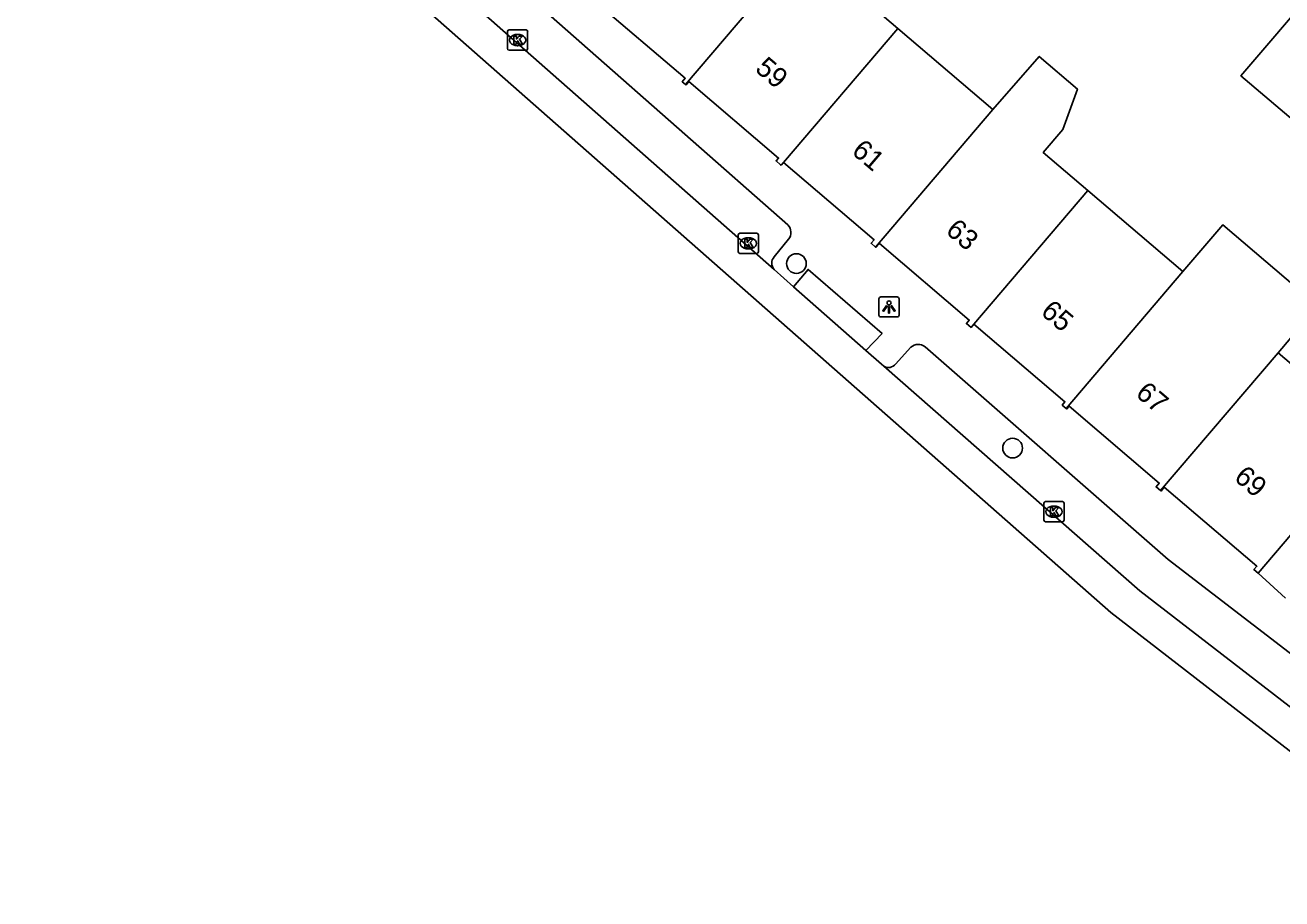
# Model space of a CAD drawing. Extents: x 162074 to 163034, y 381824 to 382557.
# Drawn here: x 162125.4 to 162187.8, y 382110.6 to 382154 of the extents above; entities that cross this region are included whole.
import ezdxf

# ---------------------------------------------------------------- set-up
doc = ezdxf.new("R2010")
doc.units = 0
for name, color, linetype in [('IMGEO_Boom', 7, 'Continuous'), ('IMGEO_Kolk', 7, 'Continuous'), ('IMGEO_Lichtpunt', 7, 'Continuous'), ('IMGEO_Pand', 7, 'Continuous'), ('IMGEO_Pand_nummerreeks', 7, 'Continuous'), ('IMGEO_Rijbaan_lokaal_gesloten', 7, 'Continuous'), ('IMGEO_Voetpad_open', 7, 'Continuous')]:
    doc.layers.add(name, color=color, linetype=linetype)

msp = doc.modelspace()

# ---------------------------------------------------------------- linework, layer by layer
at = {"layer": 'IMGEO_Boom'}
for centre in [(162163.658, 382142.201), (162174.394, 382133.032)]:
    msp.add_circle(centre, 0.489, dxfattribs=at)
at = {"layer": 'IMGEO_Kolk'}
for p, q in [((162149.309, 382152.875), (162149.309, 382153.727)), ((162149.384, 382153.801), (162150.236, 382153.801)), ((162149.797, 382153.581), (162149.822, 382153.581)), ((162150.31, 382153.727), (162150.31, 382152.875)), ((162150.236, 382152.801), (162149.384, 382152.801)), ((162149.82, 382153.021), (162149.795, 382153.021)), ((162160.769, 382142.779), (162160.769, 382143.631)), ((162160.844, 382143.705), (162161.696, 382143.705)), ((162161.257, 382143.485), (162161.282, 382143.485)), ((162161.77, 382143.631), (162161.77, 382142.779)), ((162161.696, 382142.705), (162160.844, 382142.705)), ((162161.28, 382142.925), (162161.255, 382142.925)), ((162175.946, 382129.452), (162175.946, 382130.304)), ((162176.021, 382130.378), (162176.873, 382130.378)), ((162176.434, 382130.158), (162176.459, 382130.158)), ((162176.947, 382130.304), (162176.947, 382129.452)), ((162176.457, 382129.598), (162176.432, 382129.598)), ((162176.873, 382129.378), (162176.021, 382129.378))]:
    msp.add_line(p, q, dxfattribs=at)
for points in [[(162149.309, 382152.875), (162149.309, 382153.727)], [(162149.384, 382153.801), (162150.236, 382153.801)], [(162149.63, 382153.501), (162149.753, 382153.501), (162149.753, 382153.35), (162149.883, 382153.501), (162150.047, 382153.501), (162149.901, 382153.35), (162150.054, 382153.101), (162149.902, 382153.101), (162149.817, 382153.265), (162149.753, 382153.198), (162149.753, 382153.101), (162149.63, 382153.101), (162149.63, 382153.501)], [(162150.31, 382153.727), (162150.31, 382152.875)], [(162150.236, 382152.801), (162149.384, 382152.801)], [(162160.769, 382142.779), (162160.769, 382143.631)], [(162160.844, 382143.705), (162161.696, 382143.705)], [(162161.09, 382143.405), (162161.213, 382143.405), (162161.213, 382143.254), (162161.343, 382143.405), (162161.507, 382143.405), (162161.361, 382143.254), (162161.514, 382143.005), (162161.362, 382143.005), (162161.277, 382143.169), (162161.213, 382143.102), (162161.213, 382143.005), (162161.09, 382143.005), (162161.09, 382143.405)], [(162161.77, 382143.631), (162161.77, 382142.779)], [(162161.696, 382142.705), (162160.844, 382142.705)], [(162175.946, 382129.452), (162175.946, 382130.304)], [(162176.021, 382130.378), (162176.873, 382130.378)], [(162176.947, 382130.304), (162176.947, 382129.452)], [(162176.267, 382130.078), (162176.39, 382130.078), (162176.39, 382129.927), (162176.52, 382130.078), (162176.684, 382130.078), (162176.538, 382129.927), (162176.691, 382129.678), (162176.539, 382129.678), (162176.454, 382129.842), (162176.39, 382129.775), (162176.39, 382129.678), (162176.267, 382129.678), (162176.267, 382130.078)], [(162176.873, 382129.378), (162176.021, 382129.378)]]:
    msp.add_lwpolyline(points, dxfattribs=at)
for centre, start, end in [((162149.386, 382153.725), 91.55205, 178.44795), ((162149.386, 382153.725), 91.55205, 178.44795), ((162150.234, 382153.725), 1.55205, 88.44795), ((162150.234, 382153.725), 1.55205, 88.44795), ((162149.386, 382152.877), 181.55205, 268.44795), ((162149.386, 382152.877), 181.55205, 268.44795), ((162150.234, 382152.877), 271.55205, 358.44795), ((162150.234, 382152.877), 271.55205, 358.44795), ((162160.846, 382143.629), 91.55205, 178.44795), ((162160.846, 382143.629), 91.55205, 178.44795), ((162161.694, 382143.629), 1.55205, 88.44795), ((162161.694, 382143.629), 1.55205, 88.44795), ((162160.846, 382142.781), 181.55205, 268.44795), ((162160.846, 382142.781), 181.55205, 268.44795), ((162161.694, 382142.781), 271.55205, 358.44795), ((162161.694, 382142.781), 271.55205, 358.44795), ((162176.023, 382130.302), 91.55205, 178.44795), ((162176.023, 382130.302), 91.55205, 178.44795), ((162176.871, 382130.302), 1.55205, 88.44795), ((162176.871, 382130.302), 1.55205, 88.44795), ((162176.023, 382129.454), 181.55205, 268.44795), ((162176.023, 382129.454), 181.55205, 268.44795), ((162176.871, 382129.454), 271.55205, 358.44795), ((162176.871, 382129.454), 271.55205, 358.44795)]:
    msp.add_arc(centre, 0.0765, start, end, dxfattribs=at)
for centre, major_axis, ratio, start_param, end_param in [((162149.796, 382153.301), (-0.387, 0.002), 0.722429, 4.712389, 7.853982), ((162149.821, 382153.301), (-0.39, 0.002), 0.717154, 1.570796, 4.712389), ((162161.256, 382143.205), (-0.387, 0.002), 0.722429, 4.712389, 7.853982), ((162161.281, 382143.205), (-0.39, 0.002), 0.717154, 1.570796, 4.712389), ((162176.433, 382129.878), (-0.387, 0.002), 0.722429, 4.712389, 7.853982), ((162176.458, 382129.878), (-0.39, 0.002), 0.717154, 1.570796, 4.712389)]:
    msp.add_ellipse(centre, major_axis=major_axis, ratio=ratio, start_param=start_param, end_param=end_param, dxfattribs=at)
at = {"layer": 'IMGEO_Lichtpunt'}
for p, q in [((162167.756, 382140.45), (162167.756, 382139.643)), ((162167.756, 382140.45), (162167.756, 382139.643)), ((162168.658, 382140.545), (162167.85, 382140.545)), ((162168.658, 382140.545), (162167.85, 382140.545)), ((162168.752, 382139.643), (162168.752, 382140.45)), ((162168.752, 382139.643), (162168.752, 382140.45)), ((162167.85, 382139.549), (162168.658, 382139.549)), ((162167.85, 382139.549), (162168.658, 382139.549))]:
    msp.add_line(p, q, dxfattribs=at)
for points in [[(162168.13, 382140.114), (162168.169, 382140.086), (162167.981, 382139.824), (162167.943, 382139.851), (162168.13, 382140.114)], [(162168.232, 382140.066), (162168.279, 382140.066), (162168.279, 382139.744), (162168.232, 382139.744), (162168.232, 382140.066)], [(162168.342, 382140.086), (162168.38, 382140.113), (162168.567, 382139.851), (162168.528, 382139.823), (162168.342, 382140.086)]]:
    msp.add_lwpolyline(points, dxfattribs=at)
msp.add_circle((162168.255, 382140.248), 0.0994, dxfattribs=at)
for centre, start, end in [((162167.85, 382140.45), 90, 180), ((162167.85, 382140.45), 90, 180), ((162168.658, 382140.45), 0, 90), ((162168.658, 382140.45), 0, 90), ((162167.85, 382139.643), 180, 270), ((162167.85, 382139.643), 180, 270), ((162168.658, 382139.643), 270, 0), ((162168.658, 382139.643), 270, 360)]:
    msp.add_arc(centre, 0.0946, start, end, dxfattribs=at)
at = {"layer": 'IMGEO_Pand'}
for points in [[(162158.153, 382151.091), (162163.964, 382157.908)], [(162168.686, 382153.881), (162163.964, 382157.908)], [(162189.483, 382155.926), (162185.73, 382151.525), (162188.864, 382148.853)], [(162153.434, 382155.123), (162153.479, 382155.085), (162153.62, 382155.252), (162158.136, 382151.401), (162157.99, 382151.23), (162158.153, 382151.091)], [(162163.014, 382147.226), (162168.686, 382153.881)], [(162173.408, 382149.854), (162168.686, 382153.881)], [(162178.131, 382145.828), (162175.914, 382147.718), (162176.887, 382148.859), (162177.614, 382150.868), (162175.712, 382152.49), (162173.408, 382149.854)], [(162158.153, 382151.091), (162158.179, 382151.069), (162158.322, 382151.237), (162162.772, 382147.442), (162162.649, 382147.298), (162162.871, 382147.109), (162162.896, 382147.088), (162163.014, 382147.226)], [(162173.408, 382149.854), (162167.584, 382143.021)], [(162167.584, 382143.021), (162167.365, 382143.207), (162167.517, 382143.385), (162163.014, 382147.226)], [(162172.468, 382139.192), (162178.131, 382145.828)], [(162182.853, 382141.801), (162178.131, 382145.828)], [(162187.576, 382137.774), (162189.555, 382140.097), (162184.833, 382144.124), (162182.853, 382141.801)], [(162172.468, 382139.192), (162172.327, 382139.026), (162172.095, 382139.223), (162172.243, 382139.396), (162167.778, 382143.203), (162167.607, 382143.002), (162167.584, 382143.021)], [(162182.853, 382141.801), (162177.058, 382135.002)], [(162177.058, 382135.002), (162176.858, 382135.173), (162176.994, 382135.333), (162172.468, 382139.192)], [(162181.736, 382130.922), (162187.576, 382137.774)], [(162186.59, 382126.818), (162189.835, 382130.623), (162192.514, 382133.766), (162192.327, 382133.925), (162192.227, 382133.808), (162187.576, 382137.774)], [(162181.736, 382130.922), (162181.516, 382131.11), (162181.678, 382131.3), (162177.205, 382135.114), (162177.088, 382134.977), (162177.058, 382135.002)], [(162186.59, 382126.818), (162186.379, 382126.998), (162186.524, 382127.168), (162181.926, 382131.089), (162181.763, 382130.899), (162181.736, 382130.922)]]:
    msp.add_lwpolyline(points, dxfattribs=at)
at = {"layer": 'IMGEO_Rijbaan_lokaal_gesloten'}
for points in [[(162197.645, 382110.646), (162179.272, 382124.864), (162125.354, 382172.361)], [(162133.933, 382167.137), (162162.557, 382141.907)], [(162162.557, 382141.907), (162163.514, 382141.043)], [(162163.514, 382141.043), (162167.101, 382137.877)], [(162167.101, 382137.877), (162167.885, 382137.201), (162167.996, 382137.104)], [(162167.996, 382137.104), (162180.708, 382125.942), (162198.53, 382112.194)]]:
    msp.add_lwpolyline(points, dxfattribs=at)
at = {"layer": 'IMGEO_Voetpad_open'}
for points in [[(162135.313, 382166.71), (162137.04, 382166.915), (162137.654, 382166.659), (162163.236, 382144.127)], [(162163.268, 382143.407), (162162.546, 382142.527)], [(162163.514, 382141.043), (162164.24, 382141.907), (162167.908, 382138.721), (162167.101, 382137.877)], [(162168.579, 382137.209), (162169.342, 382138.04)], [(162170.046, 382138.064), (162182.121, 382127.505), (162197.222, 382115.889)], [(162187.953, 382125.573), (162186.59, 382126.818)]]:
    msp.add_lwpolyline(points, dxfattribs=at)
for centre, radius, start, end in [((162162.823, 382143.748), 0.561, 322.55081, 42.5388), ((162162.894, 382142.223), 0.462, 138.85542, 223.17744), ((162169.708, 382137.649), 0.536, 50.84521, 133.05981), ((162168.229, 382137.482), 0.444, 238.32045, 322.09892)]:
    msp.add_arc(centre, radius, start, end, dxfattribs=at)

# ---------------------------------------------------------------- texts
at = {"layer": 'IMGEO_Pand_nummerreeks'}
for s, rotation, p in [('59', 319.54345, (162161.553, 382151.793)), ('61', 319.53863, (162166.346, 382147.696)), ('63', 319.54918, (162171.016, 382143.752)), ('65', 319.54812, (162175.738, 382139.716)), ('67', 319.54918, (162180.447, 382135.66)), ('69', 319.54345, (162185.336, 382131.492))]:
    msp.add_text(s, height=1, rotation=rotation, dxfattribs=at).set_placement(p)

doc.saveas('drawing.dxf')
